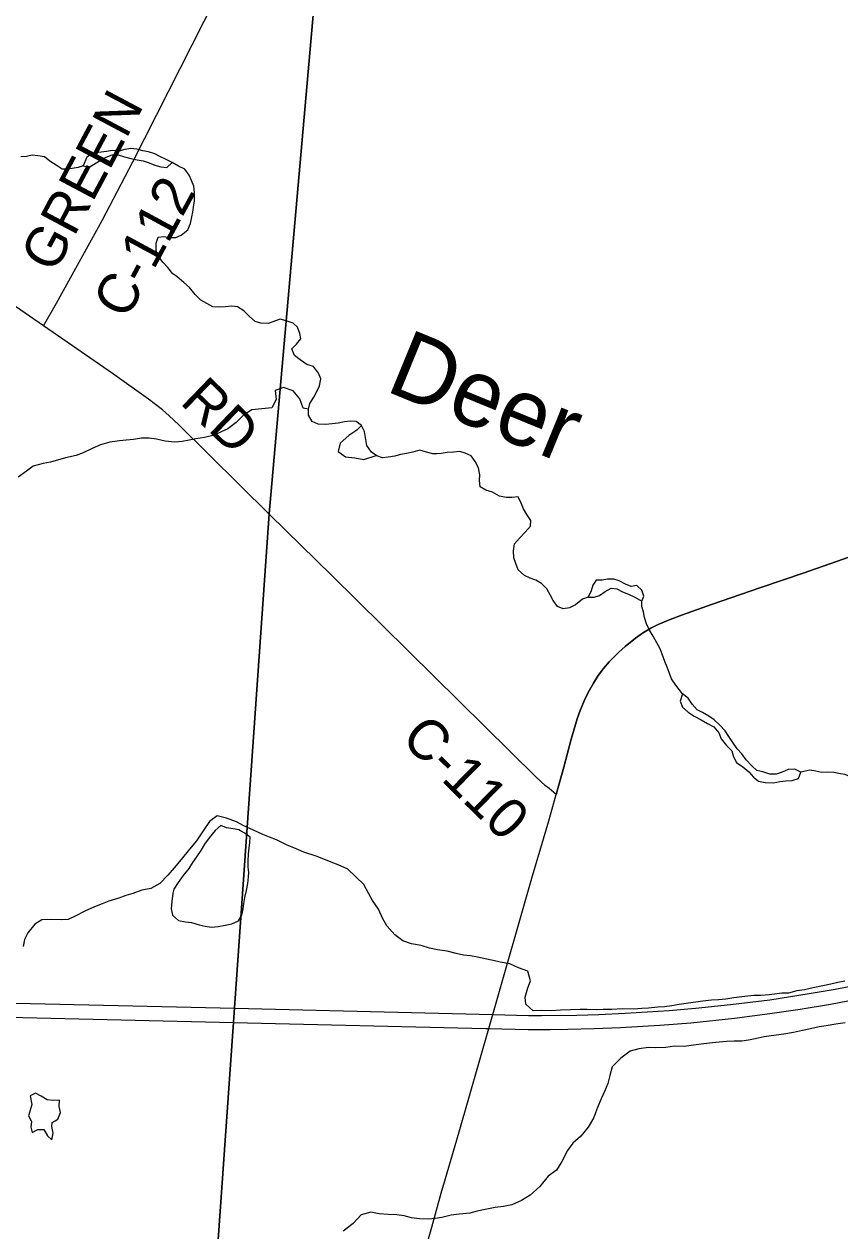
# Model space of a CAD drawing. Extents: x 0 to 36.5, y 0 to 25.3.
# Drawn here: x 6.451 to 7.602, y 17.597 to 19.299 of the extents above; entities that cross this region are included whole.
import ezdxf

# ---------------------------------------------------------------- set-up
doc = ezdxf.new("R2010")
doc.units = 0
for name, color, linetype in [('DV_X_Township_Line', 7, 'Continuous'), ('GM_X_County_Road', 7, 'Continuous'), ('GM_X_County_Road_Text', 7, 'Continuous'), ('GM_X_Interstate_Route', 7, 'Continuous'), ('GM_X_Major_River', 7, 'Continuous'), ('GM_X_Major_River_Text', 7, 'Continuous'), ('GM_X_Minor_Lake', 7, 'Continuous'), ('GM_X_Minor_River', 7, 'Continuous'), ('GM_X_State_Route', 7, 'Continuous')]:
    doc.layers.add(name, color=color, linetype=linetype)

msp = doc.modelspace()

# ---------------------------------------------------------------- linework, layer by layer
at = {"layer": 'DV_X_Township_Line'}
msp.add_lwpolyline([(5.1383, 16.6527), (6.6079, 15.9978), (6.7158, 17.4536), (6.7165, 17.4645), (6.7464, 17.8914), (6.7478, 17.9113), (6.7968, 18.6079), (6.9145, 19.9406), (6.9868, 20.9), (6.1845, 20.9)], dxfattribs=at)
msp.add_lwpolyline([(8.9, 14.8674), (8.9, 20.9), (6.9868, 20.9), (6.9145, 19.9406), (6.7968, 18.6079), (6.7478, 17.9113), (6.7464, 17.8914), (6.7165, 17.4645), (6.7158, 17.4536), (6.6079, 15.9978), (6.8419, 15.8878), (7.703, 15.458), (7.7552, 15.432), (7.7814, 15.4189), (7.8139, 15.4027), (8.0723, 15.2737), (8.5228, 15.0526)], close=True, dxfattribs=at)
at = {"layer": 'GM_X_County_Road'}
for points in [[(6.4783, 18.8731), (6.497, 18.9052), (6.5612, 19.0216), (6.6043, 19.1042), (6.7718, 19.4348), (6.8493, 19.5924), (6.8532, 19.6042), (6.8537, 19.6103), (6.8517, 19.6288), (6.8428, 19.6775), (6.8307, 19.7382), (6.8267, 19.754), (6.8166, 19.7807), (6.7369, 19.9674), (6.7287, 19.9895), (6.7013, 20.1093), (6.5819, 20.5096), (6.5776, 20.5212), (6.5695, 20.538), (6.4286, 20.8002)], [(6.4783, 18.8731), (6.4329, 18.9045), (6.3767, 18.9421), (6.3084, 18.9862), (6.27, 19.0102)], [(6.7977, 18.6066), (6.797, 18.6073), (6.6692, 18.7335), (6.6555, 18.7463), (6.6461, 18.7545), (6.6364, 18.7623), (6.6265, 18.7697), (6.5759, 18.8058), (6.5255, 18.8408), (6.4783, 18.8731)], [(7.8329, 18.6231), (7.8129, 18.6149), (7.7406, 18.5907), (7.6614, 18.5636), (7.55, 18.5246), (7.4901, 18.5041)], [(7.2015, 18.2123), (7.1916, 18.2207), (7.1866, 18.2244), (7.173, 18.2371), (6.885, 18.5212), (6.7977, 18.6066)], [(7.4901, 18.5041), (7.4207, 18.4803), (7.3797, 18.4658), (7.3623, 18.4592), (7.3452, 18.4518), (7.3352, 18.4468), (7.3235, 18.4398), (7.3133, 18.4327), (7.2987, 18.421), (7.2896, 18.4127), (7.2765, 18.3993), (7.2684, 18.3899), (7.261, 18.38), (7.2543, 18.3695), (7.2486, 18.3593), (7.2425, 18.3477), (7.24, 18.3422), (7.2352, 18.3305), (7.2311, 18.3188), (7.224, 18.295), (7.2227, 18.2902)], [(7.2227, 18.2902), (7.2123, 18.2508), (7.2015, 18.2123)]]:
    msp.add_lwpolyline(points, dxfattribs=at)
at = {"layer": 'GM_X_Interstate_Route'}
for points in [[(6.2743, 17.9219), (6.7481, 17.9108), (7.1122, 17.9021), (7.1623, 17.9009), (7.1809, 17.9008), (7.2306, 17.9013), (7.2616, 17.9022), (7.2989, 17.9039), (7.3609, 17.9079), (7.398, 17.9109), (7.4475, 17.9161), (7.5029, 17.923), (7.5582, 17.9316), (7.5949, 17.938), (7.6437, 17.9474), (7.6923, 17.9578), (7.7406, 17.9692), (7.7887, 17.9816), (8.5958, 18.2085), (8.859, 18.2822), (8.8917, 18.2927), (8.9, 18.2951)], [(7.1025, 17.8824), (7.1065, 17.8823), (7.162, 17.881), (7.1931, 17.881), (7.2179, 17.8813), (7.2552, 17.8823), (7.2924, 17.8836), (7.3479, 17.887), (7.3916, 17.8905), (7.4533, 17.8971), (7.5027, 17.9033), (7.5457, 17.9096), (7.5886, 17.9168), (7.6497, 17.9284), (7.6832, 17.9355), (7.7405, 17.9489), (7.7826, 17.9598), (7.8126, 17.968), (8.8804, 18.2679), (8.9, 18.2733)], [(4.7401, 17.9392), (5.7213, 17.9157), (5.8426, 17.9125), (5.9138, 17.9107), (6.7466, 17.8909), (7.1025, 17.8824)]]:
    msp.add_lwpolyline(points, dxfattribs=at)
at = {"layer": 'GM_X_Major_River'}
for points in [[(6.5344, 19.0986), (6.5272, 19.0964), (6.5215, 19.0956), (6.5127, 19.0941), (6.5047, 19.0941), (6.4964, 19.0995), (6.4873, 19.1052), (6.4801, 19.1113), (6.4706, 19.1129), (6.4623, 19.1136), (6.4543, 19.1118), (6.4467, 19.1114)], [(6.6601, 19.1032), (6.6514, 19.1078), (6.6434, 19.1112), (6.6355, 19.1154), (6.6264, 19.1185), (6.6184, 19.1197), (6.61, 19.122), (6.6017, 19.1231), (6.5933, 19.1216), (6.5846, 19.1194), (6.5758, 19.1202), (6.5671, 19.1187), (6.5561, 19.1176), (6.5481, 19.1164), (6.5397, 19.1111), (6.5344, 19.0986)], [(6.5344, 19.0986), (6.5427, 19.0967), (6.5587, 19.1065), (6.5667, 19.1111), (6.5751, 19.1141), (6.5838, 19.1141), (6.5925, 19.1114), (6.6016, 19.1091), (6.6107, 19.1071), (6.6191, 19.1056), (6.6274, 19.1029), (6.6354, 19.0998), (6.6438, 19.0972), (6.6525, 19.0964), (6.6601, 19.1032)], [(6.8405, 18.8253), (6.8325, 18.8314), (6.8287, 18.8405), (6.8352, 18.8473), (6.8413, 18.8549), (6.8402, 18.8625), (6.8368, 18.8713), (6.8304, 18.877), (6.8205, 18.8801), (6.8122, 18.8824), (6.7954, 18.8763), (6.7852, 18.8767), (6.7772, 18.8794), (6.7689, 18.8863), (6.7609, 18.8943), (6.7522, 18.9), (6.7438, 18.9008), (6.7347, 18.8997), (6.7252, 18.8993), (6.7173, 18.9001), (6.7006, 18.9093), (6.6922, 18.9173), (6.6843, 18.9272), (6.6763, 18.9341), (6.6665, 18.9428), (6.6608, 18.9466), (6.6536, 18.9554), (6.6468, 18.963), (6.64, 18.9718), (6.6373, 18.9794), (6.6374, 18.9896), (6.6404, 18.998), (6.648, 18.9991), (6.6568, 18.9976), (6.6651, 18.9975), (6.6727, 19.0009), (6.6819, 19.0085), (6.6857, 19.0172), (6.6876, 19.0267), (6.6892, 19.0332), (6.6907, 19.0435), (6.6915, 19.0491), (6.6915, 19.0613), (6.6904, 19.0701), (6.6874, 19.078), (6.684, 19.0857), (6.6776, 19.094), (6.6688, 19.0982), (6.6601, 19.1032)], [(7.2467, 18.4904), (7.2387, 18.4878), (7.2288, 18.4798), (7.2204, 18.4757), (7.2113, 18.4742), (7.2033, 18.4776), (7.1973, 18.4856), (7.1931, 18.494), (7.1882, 18.5024), (7.181, 18.51), (7.1727, 18.5146), (7.1651, 18.5173), (7.1567, 18.5211), (7.148, 18.5291), (7.1446, 18.5378), (7.142, 18.5462), (7.1413, 18.5557), (7.1428, 18.5656), (7.15, 18.5739), (7.158, 18.5823), (7.1653, 18.5906), (7.1657, 18.5986), (7.16, 18.607), (7.1555, 18.6153), (7.1521, 18.6233), (7.1479, 18.6321), (7.1392, 18.631), (7.1308, 18.631), (7.1214, 18.6329), (7.1119, 18.6387), (7.1024, 18.6413), (7.0944, 18.6463), (7.0933, 18.655), (7.0941, 18.663), (7.0922, 18.6729), (7.0873, 18.682), (7.0816, 18.6897), (7.0733, 18.6935), (7.0657, 18.6958), (7.0566, 18.6951), (7.0478, 18.6943), (7.0395, 18.6932), (7.0334, 18.6925), (7.0277, 18.6925), (7.0186, 18.6952), (7.0091, 18.6979), (6.9996, 18.6948), (6.9905, 18.693), (6.9821, 18.6915), (6.9738, 18.6892), (6.9646, 18.6877), (6.9567, 18.687), (6.9487, 18.6897), (6.9411, 18.695), (6.9347, 18.7042), (6.9324, 18.7156), (6.931, 18.7243), (6.9272, 18.7327), (6.9196, 18.738), (6.9109, 18.7388), (6.9029, 18.7377), (6.8941, 18.7358), (6.8858, 18.7347), (6.8763, 18.734), (6.8657, 18.7344), (6.8573, 18.7382), (6.852, 18.7473), (6.8524, 18.7557), (6.8543, 18.7637), (6.8597, 18.7724), (6.8639, 18.7804), (6.8677, 18.7887), (6.8696, 18.7982), (6.8662, 18.8066), (6.8594, 18.8157), (6.8499, 18.8188), (6.8405, 18.8253)], [(7.3222, 18.4849), (7.3253, 18.4921), (7.3226, 18.5005), (7.3154, 18.5069), (7.3075, 18.5058), (7.2995, 18.5089), (7.2904, 18.5135), (7.2828, 18.5158), (7.2741, 18.5158), (7.2665, 18.5147), (7.2581, 18.5143), (7.2532, 18.5075), (7.2509, 18.4995), (7.2467, 18.4904)], [(7.2467, 18.4904), (7.255, 18.4904), (7.2626, 18.493), (7.2706, 18.4983), (7.279, 18.5032), (7.2873, 18.5021), (7.2949, 18.4979), (7.3036, 18.4948), (7.3124, 18.4906), (7.3222, 18.4849)], [(7.3799, 18.354), (7.3701, 18.3665), (7.3641, 18.3753), (7.3607, 18.3841), (7.358, 18.392), (7.355, 18.4), (7.3512, 18.4103), (7.3482, 18.4179), (7.3433, 18.4263), (7.3384, 18.4354), (7.3331, 18.4442), (7.329, 18.4529), (7.3263, 18.4617), (7.3248, 18.4697), (7.3226, 18.4773), (7.3222, 18.4849)], [(7.3799, 18.354), (7.3765, 18.3437), (7.3795, 18.3353), (7.3878, 18.3285), (7.3962, 18.3228), (7.406, 18.3174), (7.4151, 18.3124), (7.4239, 18.3079), (7.4311, 18.2991), (7.4344, 18.2907), (7.4416, 18.2816), (7.4492, 18.274), (7.4518, 18.2652), (7.456, 18.2572), (7.4647, 18.2511), (7.4734, 18.2442), (7.4799, 18.2366), (7.4867, 18.2313), (7.4962, 18.2294), (7.5087, 18.2286), (7.5171, 18.2304), (7.5254, 18.2315), (7.5342, 18.2319), (7.5433, 18.2349), (7.5467, 18.244)], [(7.5467, 18.244), (7.5384, 18.2482), (7.5289, 18.2475), (7.5201, 18.2437), (7.5118, 18.2411), (7.5027, 18.2411), (7.4932, 18.2442), (7.4848, 18.2461), (7.4773, 18.2526), (7.4697, 18.261), (7.4632, 18.2694), (7.4568, 18.2766), (7.4508, 18.2857), (7.4451, 18.2941), (7.4398, 18.3021), (7.4326, 18.3101), (7.4243, 18.3177), (7.4167, 18.3227), (7.408, 18.328), (7.4004, 18.3319), (7.3936, 18.3395), (7.3875, 18.3479), (7.3799, 18.354)], [(7.6653, 18.2479), (7.6584, 18.2433), (7.65, 18.2384), (7.6417, 18.2365), (7.6265, 18.2366), (7.617, 18.2374), (7.6086, 18.2404), (7.6026, 18.2416), (7.5931, 18.2435), (7.5847, 18.2439), (7.5764, 18.2432), (7.5676, 18.2451), (7.5593, 18.2467), (7.5467, 18.244)]]:
    msp.add_lwpolyline(points, dxfattribs=at)
at = {"layer": 'GM_X_Minor_Lake'}
for points in [[(6.7565, 18.1609), (6.7538, 18.1623), (6.7458, 18.1639), (6.7367, 18.1654), (6.7284, 18.1688), (6.7204, 18.1613), (6.712, 18.151), (6.7055, 18.1423), (6.7002, 18.1332), (6.6941, 18.1245), (6.6887, 18.1165), (6.6834, 18.1078), (6.6754, 18.0979), (6.6685, 18.0884), (6.6624, 18.0789), (6.6609, 18.0732), (6.6593, 18.0615), (6.6585, 18.0512), (6.6604, 18.0421)], [(6.6604, 18.0421), (6.6691, 18.0344), (6.6786, 18.0329), (6.6873, 18.0317), (6.6979, 18.0287), (6.7067, 18.0267), (6.7154, 18.0252), (6.7249, 18.0263), (6.7348, 18.0282), (6.7443, 18.0301), (6.7534, 18.0342), (6.7584, 18.0422), (6.7603, 18.0509), (6.7611, 18.0585), (6.7626, 18.0669), (6.7646, 18.0767), (6.7665, 18.0866), (6.7677, 18.0961), (6.768, 18.1022), (6.7673, 18.1098), (6.7673, 18.1189), (6.7677, 18.1281), (6.7685, 18.1364), (6.7693, 18.1444), (6.7701, 18.152), (6.7625, 18.1577), (6.7565, 18.1609)], [(6.4598, 17.7872), (6.4621, 17.7754), (6.4597, 17.767), (6.4574, 17.7594), (6.4616, 17.7511), (6.4608, 17.7431), (6.4627, 17.7355), (6.4703, 17.74), (6.479, 17.74), (6.4843, 17.7312), (6.49, 17.7255), (6.4919, 17.7346), (6.4901, 17.7441), (6.4905, 17.7498), (6.4948, 17.7522)], [(6.4948, 17.7522), (6.4988, 17.7544), (6.5023, 17.7639), (6.5008, 17.7722), (6.5012, 17.7814), (6.4925, 17.781), (6.4837, 17.7818), (6.4754, 17.7871), (6.467, 17.7913), (6.4598, 17.7872)]]:
    msp.add_lwpolyline(points, dxfattribs=at)
at = {"layer": 'GM_X_Minor_River'}
for points in [[(6.8524, 18.7557), (6.8448, 18.7572), (6.8399, 18.7702), (6.8308, 18.7816), (6.8172, 18.7862), (6.805, 18.7821), (6.8065, 18.7691), (6.8004, 18.7574), (6.7863, 18.7563), (6.7723, 18.7548), (6.7605, 18.7472), (6.7502, 18.737), (6.7384, 18.7279), (6.7289, 18.7238), (6.7194, 18.7188), (6.7057, 18.7155), (6.6935, 18.7136), (6.684, 18.7121), (6.6742, 18.7098), (6.6639, 18.7091), (6.6502, 18.7107), (6.6377, 18.7134), (6.6274, 18.7149), (6.6168, 18.7146), (6.6054, 18.7127), (6.5952, 18.712), (6.5857, 18.7109), (6.572, 18.709), (6.5591, 18.7052), (6.5469, 18.7003), (6.5343, 18.6939), (6.5244, 18.6905), (6.5096, 18.6871), (6.4883, 18.6811), (6.4781, 18.6792), (6.464, 18.6751), (6.4545, 18.6683), (6.4427, 18.6596)], [(6.9272, 18.7327), (6.9203, 18.7262), (6.9089, 18.7187), (6.8971, 18.7077), (6.894, 18.6959), (6.9046, 18.6883), (6.9175, 18.6871), (6.9305, 18.6848), (6.9476, 18.6904)], [(7.5777, 17.9425), (7.564, 17.9395), (7.5519, 17.9369), (7.5412, 17.9354), (7.5291, 17.932), (7.5196, 17.9321), (7.5025, 17.9298), (7.4903, 17.9291), (7.4804, 17.9287), (7.4634, 17.9269), (7.4523, 17.9254), (7.4409, 17.9239), (7.4303, 17.9228), (7.4204, 17.9221), (7.4086, 17.921), (7.3847, 17.9176), (7.3752, 17.9161), (7.3649, 17.9143), (7.3543, 17.9128), (7.3448, 17.9124), (7.3319, 17.9109), (7.3224, 17.9106), (7.311, 17.9098), (7.295, 17.9099), (7.2798, 17.9092), (7.2677, 17.9092), (7.2582, 17.9089), (7.2453, 17.9093), (7.2354, 17.9093), (7.2217, 17.9086), (7.2077, 17.9082), (7.194, 17.9071), (7.1815, 17.9076), (7.1693, 17.9072), (7.1587, 17.9167), (7.1576, 17.9266), (7.1618, 17.9399), (7.1653, 17.9494), (7.1615, 17.9631), (7.1486, 17.9681), (7.1361, 17.9734), (7.1224, 17.9761), (7.1129, 17.9781), (7.1012, 17.9804), (7.0905, 17.9827), (7.0807, 17.9846), (7.0708, 17.9858), (7.0605, 17.9881), (7.0476, 17.9912), (7.034, 17.9931), (7.023, 17.9958), (7.0112, 17.9993), (6.9975, 18.0016), (6.9854, 18.0058), (6.974, 18.0142), (6.9627, 18.0272), (6.957, 18.0371), (6.951, 18.0504), (6.9426, 18.0626), (6.9374, 18.0721), (6.9302, 18.0854), (6.9188, 18.0961), (6.9075, 18.1071), (6.8942, 18.1129), (6.8843, 18.1171), (6.8646, 18.1247), (6.8456, 18.1309), (6.835, 18.1355), (6.8213, 18.1412), (6.8073, 18.1485), (6.7974, 18.1523), (6.788, 18.1557), (6.7747, 18.1619), (6.7603, 18.1684), (6.7508, 18.1737), (6.7368, 18.1791), (6.7235, 18.1822), (6.7128, 18.1742), (6.7037, 18.1609), (6.6941, 18.1469), (6.6846, 18.1351), (6.6728, 18.1207), (6.6629, 18.109), (6.6537, 18.0987), (6.6427, 18.087), (6.6297, 18.0798), (6.6172, 18.0772), (6.6046, 18.0726), (6.5944, 18.07), (6.5845, 18.0659), (6.5708, 18.0617), (6.5613, 18.0583), (6.5503, 18.0538), (6.5366, 18.0477), (6.524, 18.0413), (6.5134, 18.036), (6.5039, 18.0357), (6.4898, 18.0361), (6.4761, 18.0354), (6.4662, 18.0293), (6.4563, 18.0172)], [(6.4563, 18.0172), (6.4517, 18.0077), (6.4498, 17.9982)], [(7.6089, 17.9489), (7.5986, 17.947), (7.5891, 17.9448), (7.5777, 17.9425)], [(7.5825, 17.8863), (7.5726, 17.8848), (7.5605, 17.8821), (7.5491, 17.8795), (7.5361, 17.8769), (7.5228, 17.8743), (7.505, 17.872), (7.4947, 17.8706), (7.4822, 17.8679), (7.4727, 17.8657), (7.4632, 17.8646), (7.4525, 17.8646), (7.4419, 17.8639), (7.4316, 17.8631), (7.4221, 17.862), (7.4096, 17.8609), (7.3952, 17.8587), (7.3822, 17.8572), (7.3686, 17.8576), (7.3564, 17.8557), (7.3416, 17.855), (7.3317, 17.8554), (7.318, 17.8539), (7.3059, 17.8502), (7.2926, 17.8407), (7.2804, 17.8282), (7.2773, 17.8161), (7.2742, 17.805), (7.2696, 17.7933), (7.265, 17.7834), (7.2597, 17.7709), (7.2543, 17.7561), (7.2467, 17.7432), (7.2364, 17.7306), (7.225, 17.7208), (7.2177, 17.7102), (7.2097, 17.695), (7.2021, 17.6828), (7.1902, 17.6741), (7.1784, 17.6597), (7.1651, 17.6472), (7.1525, 17.64), (7.1388, 17.6336), (7.1274, 17.6314), (7.1157, 17.6299), (7.1012, 17.6272), (7.0902, 17.6246), (7.0799, 17.622), (7.0647, 17.6205), (7.0533, 17.619), (7.0404, 17.616), (7.0309, 17.6145), (7.0214, 17.6134), (7.0089, 17.6142), (6.9975, 17.6154), (6.9872, 17.6181), (6.9766, 17.6196), (6.9645, 17.62), (6.9519, 17.6208), (6.9402, 17.6235), (6.9265, 17.6194), (6.9151, 17.6076), (6.9013, 17.5966)], [(7.6091, 17.8904), (7.5958, 17.8885), (7.5825, 17.8863)]]:
    msp.add_lwpolyline(points, dxfattribs=at)
at = {"layer": 'GM_X_State_Route'}
for points in [[(7.4901, 18.5041), (7.55, 18.5246), (7.6614, 18.5636), (7.7406, 18.5907), (7.8129, 18.6149), (7.8329, 18.6231)], [(7.2227, 18.2902), (7.224, 18.295), (7.2311, 18.3188), (7.2352, 18.3305), (7.24, 18.3422), (7.2425, 18.3477), (7.2486, 18.3593), (7.2543, 18.3695), (7.261, 18.38), (7.2684, 18.3899), (7.2765, 18.3993), (7.2896, 18.4127), (7.2987, 18.421), (7.3133, 18.4327), (7.3235, 18.4398), (7.3352, 18.4468), (7.3452, 18.4518), (7.3623, 18.4592), (7.3797, 18.4658), (7.4207, 18.4803), (7.4901, 18.5041)], [(7.2015, 18.2123), (7.2123, 18.2508), (7.2227, 18.2902)], [(7.1798, 18.137), (7.191, 18.1753), (7.2015, 18.2123)], [(7.0479, 17.6787), (7.0648, 17.7368), (7.1065, 17.8823), (7.1122, 17.9021), (7.1683, 18.0978), (7.1798, 18.137)], [(6.9887, 17.4664), (6.9907, 17.4765), (6.9969, 17.5008), (7.0261, 17.6023), (7.0395, 17.6501), (7.0479, 17.6787)]]:
    msp.add_lwpolyline(points, dxfattribs=at)

# ---------------------------------------------------------------- texts
at = {"layer": 'GM_X_County_Road_Text'}
for s, rotation, p in [('GREEN', 61.9991, (6.4939, 18.9455)), ('C-112', 61.5892, (6.5957, 18.8802)), ('RD', 316.0437, (6.6695, 18.7643)), ('C-110', 315.3896, (6.9808, 18.2893))]:
    msp.add_text(s, height=0.05682, rotation=rotation, dxfattribs=at).set_placement(p)
at = {"layer": 'GM_X_Major_River_Text'}
msp.add_text('Deer', height=0.0947, rotation=337.6557, dxfattribs=at).set_placement((6.9586, 18.7822))

doc.saveas('drawing.dxf')
